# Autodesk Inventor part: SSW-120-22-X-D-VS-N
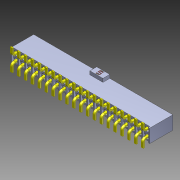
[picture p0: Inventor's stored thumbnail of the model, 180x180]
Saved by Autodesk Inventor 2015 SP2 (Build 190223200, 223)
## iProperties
Created: 2015-08
Part Number: SSW-120-22-X-D-VS-N
Material: Allgemein
Document SubType Name: Modeling
Designer: rYan
Density: 1 g/cm^3
Appearance: Vorgabe
Author: rYan
Author: jessiew
Title: \\samtec.ad\customermodels\BasicModels\iges\SSW-120-22-X-D-VS-N.igs
Description: SolidWorks IGES file using analytic representation for surfaces
Creation Date: 2013-03-19
Sending System: SolidWorks 2012
Preprocessor: SolidWorks 2012
Minimum Resolution: 0.0
Sending System Product ID: SSW-1XX-22-XXX-X-XX-XX-X-XX-ASM
Receiving System Product ID: SSW-1XX-22-XXX-X-XX-XX-X-XX-ASM
Sent Units: Inch
Translation Standard: IGES 5.3
Model Creation Time: 2013-03-19
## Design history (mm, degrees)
node "SSW-120-22-X-D-VS-N1"
node "Volumenkörper1"
node "Volumenkörper2"
node "Volumenkörper3"
node "Volumenkörper4"
node "Volumenkörper5"
node "Volumenkörper6"
node "Volumenkörper7"
node "Volumenkörper8"
node "Volumenkörper9"
node "Volumenkörper10"
node "Volumenkörper11"
node "Volumenkörper12"
node "Volumenkörper13"
node "Volumenkörper14"
node "Volumenkörper15"
node "Volumenkörper16"
node "Volumenkörper17"
node "Volumenkörper18"
node "Volumenkörper19"
node "Volumenkörper20"
node "Volumenkörper21"
node "Volumenkörper22"
node "Volumenkörper23"
node "Volumenkörper24"
node "Volumenkörper25"
node "Volumenkörper26"
node "Volumenkörper27"
node "Volumenkörper28"
node "Volumenkörper29"
node "Volumenkörper30"
node "Volumenkörper31"
node "Volumenkörper32"
node "Volumenkörper33"
node "Volumenkörper34"
node "Volumenkörper35"
node "Volumenkörper36"
node "Volumenkörper37"
node "Volumenkörper38"
node "Volumenkörper39"
node "Volumenkörper40"
node "Volumenkörper41"
node "Basis1"
node "Basis2"
node "Basis3"
node "Basis4"
node "Basis5"
node "Basis6"
node "Basis7"
node "Basis8"
node "Basis9"
node "Basis10"
node "Basis11"
node "Basis12"
node "Basis13"
node "Basis14"
node "Basis15"
node "Basis16"
node "Basis17"
node "Basis18"
node "Basis19"
node "Basis20"
node "Basis21"
node "Basis22"
node "Basis23"
node "Basis24"
node "Basis25"
node "Basis26"
node "Basis27"
node "Basis28"
node "Basis29"
node "Basis30"
node "Basis31"
node "Basis32"
node "Basis33"
node "Basis34"
node "Basis35"
node "Basis36"
node "Basis37"
node "Basis38"
node "Basis39"
node "Basis40"
node "Basis41"
